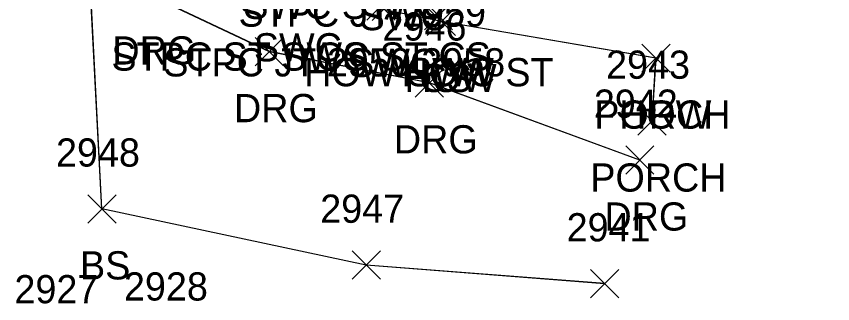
# Model space of a CAD drawing. Extents: x 1554668 to 1563881, y 831386 to 834374.
# Drawn here: x 1562303.4 to 1562361.2, y 832819.7 to 832840.1 of the extents above; entities that cross this region are included whole.
import ezdxf

# ---------------------------------------------------------------- set-up
doc = ezdxf.new("R2010")
doc.units = 0
for name, color, linetype in [('L_A', 7, 'Continuous'), ('L_I', 7, 'Continuous'), ('L_TIC', 7, 'Continuous'), ('LBC', 7, 'Continuous'), ('LBF', 7, 'Continuous'), ('LELB', 7, 'Continuous'), ('R_A', 7, 'Continuous'), ('R_I', 7, 'Continuous'), ('R_TIC', 7, 'Continuous'), ('RDG', 7, 'Continuous')]:
    doc.layers.add(name, color=color, linetype=linetype)

msp = doc.modelspace()

# ---------------------------------------------------------------- linework, layer by layer
at = {"layer": 'L_TIC'}
for points in [[(1562328.218, 832839.804), (1562330.218, 832841.804)], [(1562330.218, 832839.804), (1562328.218, 832841.804)], [(1562332.289, 832839.105), (1562334.289, 832841.105)], [(1562334.289, 832839.105), (1562332.289, 832841.105)], [(1562332.495, 832838.697), (1562334.495, 832840.697)], [(1562334.495, 832838.697), (1562332.495, 832840.697)], [(1562332.495, 832838.697), (1562334.495, 832840.697)], [(1562334.495, 832838.697), (1562332.495, 832840.697)], [(1562347.708, 832836.101), (1562349.708, 832838.101)], [(1562349.708, 832836.101), (1562347.708, 832838.101)], [(1562347.708, 832836.101), (1562349.708, 832838.101)], [(1562349.708, 832836.101), (1562347.708, 832838.101)], [(1562347.428, 832831.639), (1562349.428, 832833.639)], [(1562349.428, 832831.639), (1562347.428, 832833.639)], [(1562308.438, 832825.413), (1562310.438, 832827.413)], [(1562310.438, 832825.413), (1562308.438, 832827.413)], [(1562327.168, 832821.43), (1562329.168, 832823.43)], [(1562329.168, 832821.43), (1562327.168, 832823.43)], [(1562344.066, 832820.112), (1562346.066, 832822.112)], [(1562346.066, 832820.112), (1562344.066, 832822.112)]]:
    msp.add_lwpolyline(points, dxfattribs=at)
at = {"layer": 'LBC'}
for points in [[(1562348.708, 832837.101), (1562333.495, 832839.697), (1562333.289, 832840.105), (1562338.688, 832868.767), (1562339.022, 832870.169), (1562354.286, 832867.426), (1562355.697, 832875.149), (1562361.174, 832874.604)], [(1562348.707, 832837.107), (1562333.497, 832839.702), (1562333.291, 832840.109), (1562338.692, 832868.77), (1562339.03, 832870.172), (1562354.287, 832867.43), (1562355.704, 832875.152), (1562361.18, 832874.607)], [(1562348.707, 832837.107), (1562333.497, 832839.702), (1562333.291, 832840.109), (1562338.692, 832868.77), (1562339.03, 832870.172), (1562354.287, 832867.43), (1562355.704, 832875.152), (1562361.18, 832874.607)], [(1562348.707, 832837.107), (1562333.497, 832839.702), (1562333.291, 832840.109), (1562338.692, 832868.77), (1562339.03, 832870.172), (1562354.287, 832867.43), (1562355.704, 832875.152), (1562361.18, 832874.607)]]:
    msp.add_lwpolyline(points, dxfattribs=at)
at = {"layer": 'LBF'}
for points in [[(1562348.428, 832832.639), (1562348.708, 832837.101)], [(1562348.433, 832832.642), (1562348.707, 832837.107)], [(1562348.433, 832832.642), (1562348.707, 832837.107)], [(1562348.433, 832832.642), (1562348.707, 832837.107)]]:
    msp.add_lwpolyline(points, dxfattribs=at)
at = {"layer": 'LELB'}
for points in [[(1562345.066, 832821.112), (1562328.168, 832822.43), (1562309.438, 832826.413), (1562308.441, 832845.419), (1562303.579, 832849.623), (1562307.988, 832869.591), (1562313.466, 832890.153), (1562313.472, 832898.332), (1562314.73, 832910.862), (1562317.581, 832930.381), (1562320.996, 832947.887), (1562324.106, 832958.922), (1562330.263, 832960.897), (1562340.381, 832959.143), (1562362.819, 832956.013), (1562385.379, 832952.948)], [(1562345.069, 832821.116), (1562328.169, 832822.436), (1562309.438, 832826.42), (1562308.447, 832845.421), (1562303.585, 832849.625), (1562307.987, 832869.596), (1562313.465, 832890.156), (1562313.48, 832898.336), (1562314.731, 832910.865), (1562317.583, 832930.384), (1562320.998, 832947.891), (1562324.105, 832958.919), (1562330.263, 832960.896), (1562340.381, 832959.138), (1562362.817, 832956.015), (1562385.382, 832952.946)], [(1562345.069, 832821.116), (1562328.169, 832822.436), (1562309.438, 832826.42), (1562308.447, 832845.421), (1562303.585, 832849.625), (1562307.987, 832869.596), (1562313.465, 832890.156), (1562313.48, 832898.336), (1562314.731, 832910.865), (1562317.583, 832930.384), (1562320.998, 832947.891), (1562324.105, 832958.919), (1562330.263, 832960.896), (1562340.381, 832959.138), (1562362.817, 832956.015), (1562385.382, 832952.946)], [(1562345.069, 832821.116), (1562328.169, 832822.436), (1562309.438, 832826.42), (1562308.447, 832845.421), (1562303.585, 832849.625), (1562307.987, 832869.596), (1562313.465, 832890.156), (1562313.48, 832898.336), (1562314.731, 832910.865), (1562317.583, 832930.384), (1562320.998, 832947.891), (1562324.105, 832958.919), (1562330.263, 832960.896), (1562340.381, 832959.138), (1562362.817, 832956.015), (1562385.382, 832952.946)], [(1562333.495, 832839.697), (1562326.121, 832841.214)]]:
    msp.add_lwpolyline(points, dxfattribs=at)
at = {"layer": 'R_TIC'}
for points in [[(1562328.59, 832839.764), (1562330.59, 832841.764)], [(1562330.59, 832839.764), (1562328.59, 832841.764)], [(1562332.289, 832839.105), (1562334.289, 832841.105)], [(1562334.289, 832839.105), (1562332.289, 832841.105)], [(1562320.305, 832836.56), (1562322.305, 832838.56)], [(1562322.305, 832836.56), (1562320.305, 832838.56)], [(1562331.639, 832834.346), (1562333.639, 832836.346)], [(1562333.639, 832834.346), (1562331.639, 832836.346)], [(1562346.563, 832828.876), (1562348.563, 832830.876)], [(1562348.563, 832828.876), (1562346.563, 832830.876)]]:
    msp.add_lwpolyline(points, dxfattribs=at)
at = {"layer": 'RDG'}
for points in [[(1562347.563, 832829.876), (1562332.639, 832835.346), (1562321.305, 832837.56), (1562312.687, 832841.648), (1562308.441, 832845.419)], [(1562347.57, 832829.878), (1562332.644, 832835.348), (1562321.312, 832837.561), (1562312.693, 832841.65), (1562308.447, 832845.421)], [(1562347.57, 832829.878), (1562332.644, 832835.348), (1562321.312, 832837.561), (1562312.693, 832841.65), (1562308.447, 832845.421)], [(1562347.57, 832829.878), (1562332.644, 832835.348), (1562321.312, 832837.561), (1562312.693, 832841.65), (1562308.447, 832845.421)]]:
    msp.add_lwpolyline(points, dxfattribs=at)

# ---------------------------------------------------------------- texts
at = {"layer": 'L_A'}
for s, p in [('SWC STPC', (1562319.454, 832839.881)), ('STPC JT 2959', (1562319.119, 832839.333)), ('STPC ST SWC ST CS', (1562310.106, 832836.214)), ('CS', (1562324.562, 832836.214)), ('STPC JT 2950 2958', (1562313.784, 832835.804)), ('HOW', (1562330.675, 832835.105)), ('HOW', (1562330.881, 832834.697)), ('CS', (1562331.936, 832834.697)), ('PORCH', (1562344.33, 832832.101)), ('HOW', (1562346.094, 832832.101)), ('PORCH', (1562344.05, 832827.639)), ('BS', (1562307.879, 832821.413))]:
    msp.add_text(s, height=2, dxfattribs=at).set_placement(p)
at = {"layer": 'L_I'}
for s, p in [('2943', (1562345.168, 832835.639)), ('2948', (1562306.178, 832829.413)), ('2947', (1562324.908, 832825.43)), ('2941', (1562342.373, 832824.112)), ('2927', (1562303.232, 832819.724))]:
    msp.add_text(s, height=2, dxfattribs=at).set_placement(p)
at = {"layer": 'R_A'}
for s, p in [('SWC STPC', (1562319.454, 832839.881)), ('SWC', (1562327.701, 832839.081)), ('SWC', (1562320.204, 832836.87)), ('STPC ST SWC ST CS', (1562310.106, 832836.214)), ('DRG', (1562310.175, 832836.648)), ('SWC', (1562326.953, 832835.764)), ('HOW SWC ST', (1562323.77, 832835.105)), ('DRG', (1562318.793, 832832.56)), ('DRG', (1562330.127, 832830.346)), ('DRG', (1562345.052, 832824.876))]:
    msp.add_text(s, height=2, dxfattribs=at).set_placement(p)
at = {"layer": 'R_I'}
for s, p in [('2946', (1562329.324, 832838.346)), ('2942', (1562344.304, 832832.876)), ('2928', (1562310.994, 832819.918)), ('2927', (1562303.232, 832819.724)), ('2927', (1562303.232, 832819.724))]:
    msp.add_text(s, height=2, dxfattribs=at).set_placement(p)

doc.saveas('drawing.dxf')
